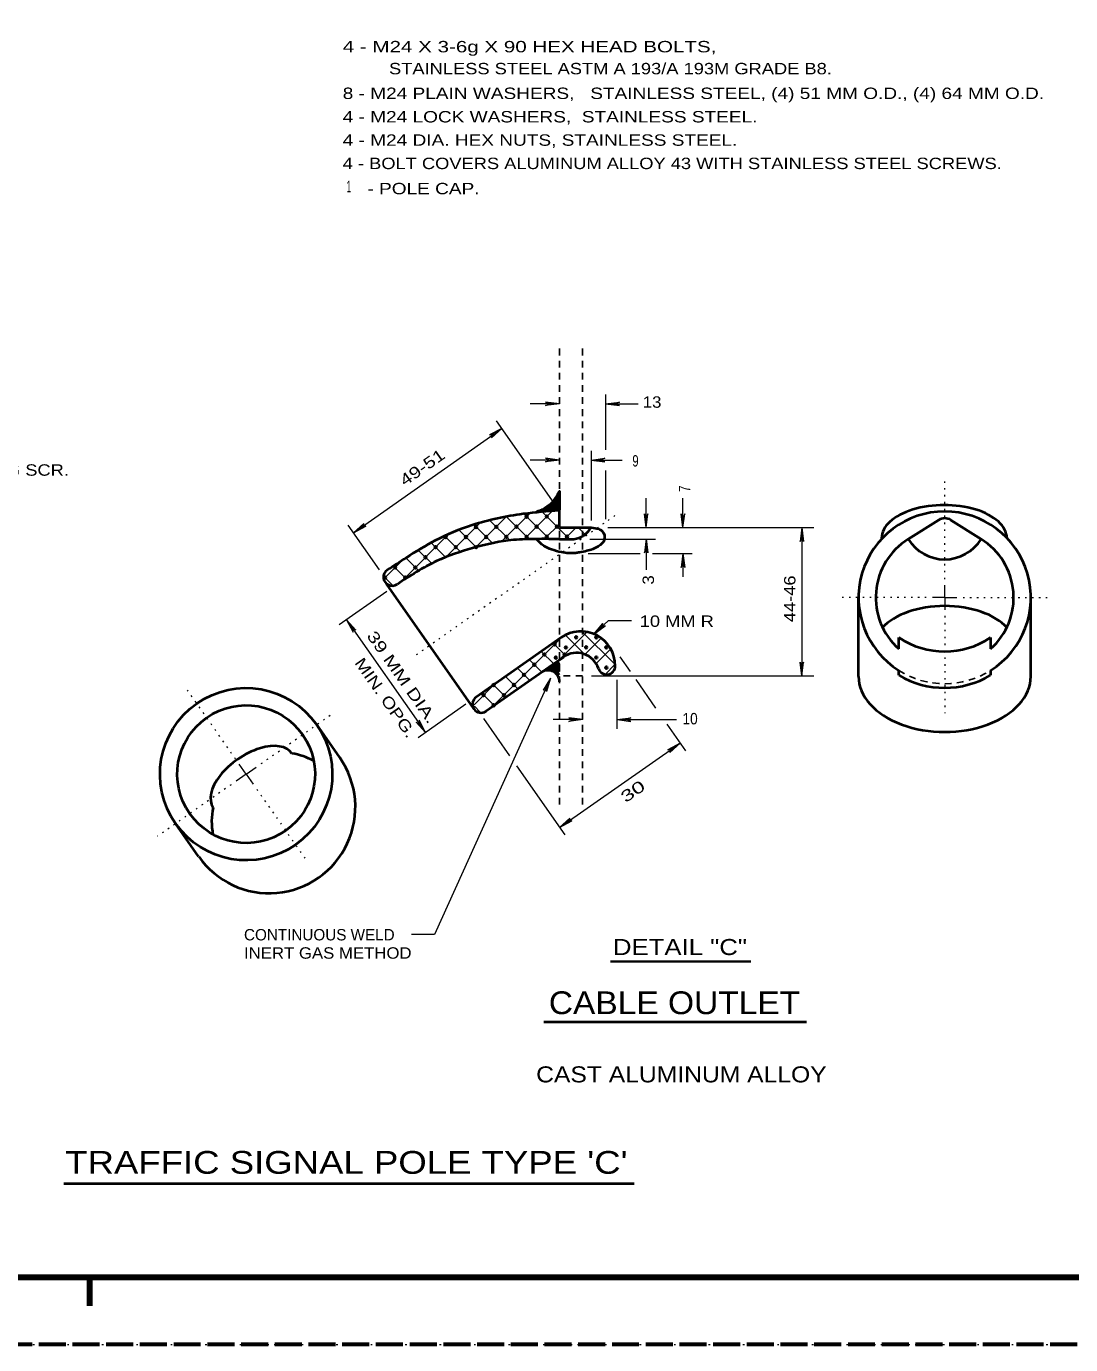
# Model space of a CAD drawing. Extents: x 312583 to 312854, y 144419 to 144597.
# Drawn here: x 312723.1 to 312792.8, y 144418.6 to 144506.5 of the extents above; entities that cross this region are included whole.
import ezdxf
from ezdxf.enums import TextEntityAlignment as Align

# ---------------------------------------------------------------- set-up
doc = ezdxf.new("R2010")
doc.units = 0
doc.header["$LTSCALE"] = 0.3
doc.header["$PDMODE"] = 32
doc.header["$PDSIZE"] = 0.15
for name, pattern in [('DOTTED', [1.5, 0.3, -1.2]), ('LONG_DASHED', [7.5, 6, -1.5]), ('SHORT_DASHED', [2.7, 1.5, -1.2])]:
    doc.linetypes.add(name, pattern=pattern)
for name, color, linetype, lineweight in [('1', 7, 'Continuous', 35), ('2', 7, 'Continuous', 13), ('62', 7, 'DOTTED', 13), ('63', 7, 'LONG_DASHED', 60)]:
    doc.layers.add(name, color=color, linetype=linetype, lineweight=lineweight)

msp = doc.modelspace()

# ---------------------------------------------------------------- linework, layer by layer
at = {"layer": '1', "linetype": 'SHORT_DASHED', "lineweight": 25}
for p, q in [((312758.6957, 144454.6164), (312758.6957, 144485.3597)), ((312760.229, 144454.6164), (312760.229, 144485.3597)), ((312760.229, 144463.1954), (312758.6957, 144463.1954))]:
    msp.add_line(p, q, dxfattribs=at)
at = {"layer": '1', "linetype": 'DOTTED', "lineweight": 13}
msp.add_line((312762.3987, 144473.8981), (312748.9897, 144464.4987), dxfattribs=at)
at = {"layer": '1', "lineweight": 13}
for p, q in [((312753.0913, 144471.7591), (312755.1077, 144473.7831)), ((312754.8547, 144472.1807), (312756.733, 144474.0591)), ((312756.6487, 144472.3341), (312755.192, 144473.7907)), ((312756.3267, 144472.3111), (312758.2203, 144474.2047)), ((312757.975, 144472.3571), (312756.342, 144473.9977)), ((312759.3397, 144472.3417), (312757.5457, 144474.1511)), ((312751.1747, 144471.1841), (312753.3597, 144473.3691)), ((312753.1527, 144471.7667), (312751.9567, 144472.9704)), ((312754.2413, 144472.0351), (312753.007, 144473.2694)), ((312755.3837, 144472.2497), (312754.0573, 144473.5684)), ((312757.722, 144472.3571), (312758.688, 144473.3231)), ((312759.0483, 144472.3417), (312759.7997, 144473.0931)), ((312760.3363, 144472.7021), (312759.9453, 144473.1007)), ((312748.1923, 144469.5511), (312751.3203, 144472.6791)), ((312751.0673, 144471.1457), (312750.132, 144472.0887)), ((312752.087, 144471.4831), (312751.0367, 144472.5334)), ((312749.281, 144470.2257), (312748.4377, 144471.0691)), ((312750.155, 144470.7164), (312749.2733, 144471.5904)), ((312747.004, 144469.7044), (312748.269, 144470.9694)), ((312748.4453, 144469.7044), (312747.6173, 144470.5324)), ((312747.5407, 144469.2674), (312746.9963, 144469.8117)), ((312754.1723, 144461.1101), (312758.872, 144465.8097)), ((312758.6497, 144464.2457), (312760.5433, 144466.1317)), ((312760.3977, 144464.6367), (312759.0713, 144465.9477)), ((312762.4217, 144463.9697), (312760.1907, 144466.1701)), ((312759.102, 144464.5677), (312758.2817, 144465.3881)), ((312760.3823, 144464.6367), (312761.471, 144465.7254)), ((312761.1337, 144464.0311), (312762.115, 144465.0124)), ((312757.515, 144463.4484), (312756.687, 144464.2764)), ((312758.3123, 144464.0004), (312757.4843, 144464.8361)), ((312755.9203, 144462.3367), (312755.0923, 144463.1647)), ((312756.7177, 144462.8887), (312755.8897, 144463.7244)), ((312761.7393, 144463.3027), (312762.4217, 144463.9851)), ((312752.9993, 144461.2787), (312754.387, 144462.6664)), ((312755.1307, 144461.7694), (312754.3027, 144462.5974)), ((312754.3333, 144461.2174), (312753.5053, 144462.0454)), ((312753.4057, 144460.7881), (312753.03, 144461.1714))]:
    msp.add_line(p, q, dxfattribs=at)
at = {"layer": '1', "lineweight": 40}
for p, q in [((312758.6957, 144473.0931), (312758.6957, 144474.2431)), ((312758.6957, 144473.0931), (312760.804, 144473.0931)), ((312783.9957, 144473.5991), (312781.9563, 144472.3264)), ((312784.8083, 144473.5991), (312786.84, 144472.3264)), ((312758.6957, 144472.3264), (312759.654, 144472.3264)), ((312752.9533, 144461.0487), (312747.1497, 144469.3517)), ((312778.652, 144463.1647), (312778.652, 144468.4241)), ((312790.1443, 144463.1647), (312790.1443, 144468.4241)), ((312758.803, 144465.7561), (312753.1297, 144461.7924)), ((312781.3353, 144464.9971), (312781.3353, 144465.7561)), ((312787.4687, 144464.9971), (312787.4687, 144465.7561)), ((312758.9563, 144464.4604), (312753.7967, 144460.8417)), ((312757.4843, 144463.4331), (312758.9563, 144464.4604)), ((312757.9443, 144463.5711), (312758.6957, 144464.0924)), ((312758.1513, 144463.5404), (312758.6957, 144463.9161)), ((312758.3123, 144463.4714), (312758.6957, 144463.7397)), ((312758.435, 144463.3794), (312758.6957, 144463.5557)), ((312758.5347, 144463.2721), (312758.6957, 144463.3871)), ((312758.619, 144463.1417), (312758.6957, 144463.2031)), ((312781.3353, 144463.2414), (312781.3353, 144463.5711)), ((312787.4687, 144463.2414), (312787.4687, 144463.5711)), ((312744.037, 144457.7521), (312742.496, 144459.9524)), ((312734.6147, 144451.1511), (312733.0737, 144453.3437)), ((312763.6794, 144429.3029), (312725.619, 144429.3029))]:
    msp.add_line(p, q, dxfattribs=at)
at = {"layer": '1', "lineweight": 158}
for p, q in [((312616.5, 144423.0846), (312849, 144423.0846)), ((312727.35, 144421.1646), (312727.35, 144423.0846))]:
    msp.add_line(p, q, dxfattribs=at)
at = {"layer": '1', "lineweight": 40}
for centre, radius, start, end in [((312784.4005, 144468.4256), 5.7469, 302.26476, 237.73524), ((312784.4005, 144472.9493), 0.7667, 57.96874, 122.03126), ((312759.4572, 144473.8705), 1.5564, 277.20711, 330.03225), ((312784.4005, 144468.4256), 4.6, 122.03776, 228.18882), ((312784.4005, 144473.8536), 2.8794, 212.03126, 327.96874), ((312784.4005, 144468.4256), 4.6, 311.81031, 57.96224), ((312747.5267, 144469.7894), 0.5768, 125.00164, 305.00164), ((312760.1186, 144463.871), 2.3, 0, 125.01416), ((312784.4005, 144470.3718), 5.5403, 236.39125, 303.60875), ((312759.8395, 144463.2042), 1.5333, 18.24978, 124.99202), ((312757.929, 144462.8037), 0.7667, 0, 125.00321), ((312761.8421, 144463.8685), 0.5765, 198.353, 0), ((312784.4005, 144468.4256), 6.0201, 239.38652, 300.62404), ((312753.4639, 144461.3171), 0.5768, 125.04193, 305.04193)]:
    msp.add_arc(centre, radius, start, end, dxfattribs=at)
at = {"layer": '1', "linetype": 'SHORT_DASHED', "lineweight": 25}
msp.add_arc((312784.4005, 144468.4256), 5.7469, 237.73524, 302.26476, dxfattribs=at)
at = {"layer": '1', "lineweight": 40}
for centre, major_axis, ratio, start_param, end_param in [((312784.3667, 144472.3877), (4.1799, 0.0061), 0.5283, 6.2831853, 9.424778), ((312784.4005, 144465.3099), (-4.5969, 0), 0.555704, 3.5912894, 5.8336047), ((312784.4005, 144463.1632), (-5.7469, 0), 0.64461, 6.2831853, 9.424778), ((312738.1981, 144456.2417), (-2.6189, -1.8001), 0.537251, 3.1255912, 6.2961342), ((312740.081, 144453.5001), (-3.7634, -2.6378), 0.999836, 3.598371, 3.9338982), ((312739.3266, 144454.4508), (-4.7079, -3.3002), 0.999869, 0.0001305, 3.1417232), ((312740.081, 144453.5001), (-3.7634, -2.6378), 0.999836, 5.4703118, 5.8646097)]:
    msp.add_ellipse(centre, major_axis=major_axis, ratio=ratio, start_param=start_param, end_param=end_param, dxfattribs=at)
for major_axis, ratio in [((-4.7079, -3.3002), 0.999869), ((-3.7634, -2.6378), 0.999836)]:
    msp.add_ellipse((312737.7871, 144456.6465), major_axis=major_axis, ratio=ratio, dxfattribs=at)
for points in [[(312758.6957, 144474.2431), (312756.273, 144474.0054), (312752.869, 144473.2541), (312750.3927, 144472.2267), (312748.4683, 144471.0844), (312747.1957, 144470.2564)], [(312760.804, 144473.0931), (312761.3253, 144473.0011), (312761.5323, 144472.8784), (312761.6857, 144472.2727), (312761.287, 144471.8357), (312760.5203, 144471.5367), (312760.0297, 144471.4371), (312759.7843, 144471.3987), (312758.8337, 144471.4524), (312758.159, 144471.6364), (312757.653, 144471.8817), (312757.1777, 144472.3111)], [(312758.6957, 144472.3264), (312756.8097, 144472.3264), (312755.2457, 144472.2267), (312752.892, 144471.7207), (312750.5153, 144470.8697), (312747.855, 144469.3134)]]:
    msp.add_spline(points, degree=3, dxfattribs=at)
at = {"layer": '1'}
for p in [(312756.503, 144473.8291), (312757.8523, 144473.8367), (312753.1297, 144473.1391), (312754.479, 144473.1467), (312755.8283, 144473.1544), (312757.1777, 144473.1621), (312758.527, 144473.1621), (312751.1057, 144472.4644), (312752.455, 144472.4644), (312753.8043, 144472.4721), (312755.1537, 144472.4797), (312756.503, 144472.4797), (312757.8523, 144472.4874), (312759.2017, 144472.4951), (312749.7563, 144471.1151), (312750.431, 144471.7897), (312751.7803, 144471.7897), (312753.1297, 144471.7897), (312747.7323, 144470.4327), (312749.0817, 144470.4327), (312747.05, 144469.7504), (312748.3993, 144469.7581), (312759.8073, 144465.7714), (312761.1567, 144465.7791), (312758.366, 144465.3037), (312759.125, 144465.0967), (312760.4743, 144465.1044), (312761.8237, 144465.1044), (312757.0167, 144463.9467), (312757.6913, 144464.6291), (312758.4503, 144464.4221), (312759.0407, 144464.6291), (312761.149, 144464.4297), (312756.3343, 144463.2721), (312761.8237, 144463.7551), (312754.3103, 144462.5897), (312755.6597, 144462.5974), (312753.6357, 144461.9151), (312754.985, 144461.9151), (312754.3027, 144461.2404)]:
    msp.add_point(p, dxfattribs=at)
at = {"layer": '2'}
for p, q in [((312761.7623, 144481.9634), (312761.7623, 144478.2834)), ((312758.6957, 144481.3501), (312756.7407, 144481.3501)), ((312757.768, 144481.4651), (312758.067, 144481.3501)), ((312758.6957, 144481.3501), (312757.768, 144481.4651)), ((312757.768, 144481.2351), (312758.067, 144481.3501)), ((312758.6957, 144481.3501), (312757.768, 144481.2351)), ((312761.7623, 144481.3501), (312762.69, 144481.4651)), ((312761.7623, 144481.3501), (312763.9414, 144481.3501)), ((312761.7623, 144481.3501), (312762.69, 144481.2351)), ((312762.69, 144481.4651), (312762.391, 144481.3501)), ((312762.69, 144481.2351), (312762.391, 144481.3501)), ((312758.3507, 144474.7337), (312754.4943, 144480.2231)), ((312744.9417, 144472.7481), (312754.847, 144479.7171)), ((312754.847, 144479.7171), (312754.0267, 144479.2801)), ((312754.0267, 144479.2801), (312754.3333, 144479.3567)), ((312754.847, 144479.7171), (312754.157, 144479.0884)), ((312754.157, 144479.0884), (312754.3333, 144479.3567)), ((312760.804, 144478.2144), (312760.804, 144473.5607)), ((312758.6957, 144477.6011), (312756.7407, 144477.6011)), ((312757.768, 144477.7161), (312758.067, 144477.6011)), ((312758.6957, 144477.6011), (312757.768, 144477.7161)), ((312757.768, 144477.4861), (312758.067, 144477.6011)), ((312758.6957, 144477.6011), (312757.768, 144477.4861)), ((312760.804, 144477.6011), (312761.7317, 144477.7161)), ((312760.804, 144477.6011), (312762.8784, 144477.6011)), ((312760.804, 144477.6011), (312761.7317, 144477.4861)), ((312761.7317, 144477.7161), (312761.4403, 144477.6011)), ((312761.7317, 144477.4861), (312761.4403, 144477.6011)), ((312761.7623, 144476.9111), (312761.7623, 144473.6681)), ((312764.484, 144473.0931), (312764.484, 144475.0481)), ((312766.9373, 144473.0931), (312766.9373, 144475.0481)), ((312764.369, 144474.0207), (312764.484, 144473.7217)), ((312764.484, 144473.0931), (312764.369, 144474.0207)), ((312764.599, 144474.0207), (312764.484, 144473.7217)), ((312764.484, 144473.0931), (312764.599, 144474.0207)), ((312766.8223, 144474.0207), (312766.9373, 144473.7217)), ((312766.9373, 144473.0931), (312766.8223, 144474.0207)), ((312767.0523, 144474.0207), (312766.9373, 144473.7217)), ((312766.9373, 144473.0931), (312767.0523, 144474.0207)), ((312746.682, 144470.2794), (312744.589, 144473.2541)), ((312744.9417, 144472.7481), (312745.6393, 144473.3767)), ((312744.9417, 144472.7481), (312745.7697, 144473.1851)), ((312745.6393, 144473.3767), (312745.463, 144473.1084)), ((312745.7697, 144473.1851), (312745.463, 144473.1084)), ((312761.931, 144473.0931), (312775.662, 144473.0931)), ((312774.8723, 144473.0931), (312774.7497, 144472.1654)), ((312774.8723, 144473.0931), (312774.8723, 144463.1954)), ((312774.8723, 144473.0931), (312774.9873, 144472.1654)), ((312760.7273, 144472.3264), (312765.0973, 144472.3264)), ((312764.484, 144472.3341), (312764.369, 144471.4064)), ((312764.484, 144472.3341), (312764.484, 144470.2863)), ((312764.484, 144472.3341), (312764.599, 144471.4064)), ((312774.7497, 144472.1654), (312774.8723, 144472.4644)), ((312774.9873, 144472.1654), (312774.8723, 144472.4644)), ((312760.62, 144471.3681), (312764.0853, 144471.3681)), ((312764.369, 144471.4064), (312764.484, 144471.6977)), ((312764.599, 144471.4064), (312764.484, 144471.6977)), ((312764.9133, 144471.3681), (312767.5507, 144471.3681)), ((312766.9373, 144471.3604), (312766.8223, 144470.4404)), ((312766.9373, 144471.3604), (312766.9373, 144469.8117)), ((312766.9373, 144471.3604), (312767.0523, 144470.4404)), ((312766.8223, 144470.4404), (312766.9373, 144470.7317)), ((312767.0523, 144470.4404), (312766.9373, 144470.7317)), ((312747.1727, 144468.8381), (312743.9833, 144466.5994)), ((312784.402, 144468.4241), (312783.5817, 144468.4241)), ((312784.402, 144468.4241), (312784.402, 144469.2444)), ((312784.402, 144468.4241), (312784.402, 144469.2444)), ((312784.402, 144468.4241), (312785.2147, 144468.4241)), ((312784.402, 144468.4241), (312784.402, 144467.6114)), ((312744.4817, 144466.9444), (312749.764, 144459.4234)), ((312744.4817, 144466.9444), (312744.9187, 144466.1241)), ((312744.4817, 144466.9444), (312745.1103, 144466.2544)), ((312760.9957, 144465.9937), (312761.9693, 144466.9061)), ((312760.9957, 144465.9937), (312761.5937, 144466.7067)), ((312761.5937, 144466.7067), (312761.4557, 144466.4231)), ((312761.9693, 144466.9061), (312763.5027, 144466.9061)), ((312744.9187, 144466.1241), (312744.8497, 144466.4307)), ((312745.1103, 144466.2544), (312744.8497, 144466.4307)), ((312760.9957, 144465.9937), (312761.747, 144466.5457)), ((312761.747, 144466.5457), (312761.4557, 144466.4231)), ((312762.7283, 144464.4757), (312763.4183, 144463.4867)), ((312774.7497, 144464.1231), (312774.8723, 144463.8241)), ((312774.8723, 144463.1954), (312774.7497, 144464.1231)), ((312774.9873, 144464.1231), (312774.8723, 144463.8241)), ((312774.8723, 144463.1954), (312774.9873, 144464.1231)), ((312760.8423, 144463.1954), (312775.662, 144463.1954)), ((312758.0977, 144463.0421), (312750.362, 144445.9377)), ((312758.0977, 144463.0421), (312757.6147, 144462.2447)), ((312757.6147, 144462.2447), (312757.8447, 144462.4671)), ((312758.0977, 144463.0421), (312757.8217, 144462.1527)), ((312757.8217, 144462.1527), (312757.8447, 144462.4671)), ((312762.529, 144462.9271), (312762.529, 144459.6687)), ((312763.794, 144462.9501), (312765.1127, 144461.0564)), ((312752.455, 144461.3094), (312749.2657, 144459.0707)), ((312749.143, 144460.1134), (312749.4037, 144459.9371)), ((312749.764, 144459.4234), (312749.143, 144460.1134)), ((312749.327, 144460.2437), (312749.4037, 144459.9371)), ((312749.764, 144459.4234), (312749.327, 144460.2437)), ((312753.6357, 144460.3511), (312755.3683, 144457.8671)), ((312760.2443, 144460.2821), (312758.2817, 144460.2821)), ((312759.3167, 144460.3971), (312759.608, 144460.2821)), ((312760.2443, 144460.2821), (312759.3167, 144460.3971)), ((312759.3167, 144460.1671), (312759.608, 144460.2821)), ((312760.2443, 144460.2821), (312759.3167, 144460.1671)), ((312762.5367, 144460.2821), (312763.4643, 144460.3971)), ((312762.5367, 144460.2821), (312766.4934, 144460.2821)), ((312762.5367, 144460.2821), (312763.4643, 144460.1671)), ((312763.4643, 144460.3971), (312763.1653, 144460.2821)), ((312763.4643, 144460.1671), (312763.1653, 144460.2821)), ((312765.8563, 144459.9907), (312767.0983, 144458.2044)), ((312758.7033, 144453.0907), (312766.7457, 144458.7104)), ((312766.7457, 144458.7104), (312765.9253, 144458.2734)), ((312765.9253, 144458.2734), (312766.232, 144458.3501)), ((312766.7457, 144458.7104), (312766.0557, 144458.0817)), ((312766.0557, 144458.0817), (312766.232, 144458.3501)), ((312737.7887, 144456.6481), (312737.321, 144457.3151)), ((312737.7887, 144456.6481), (312737.321, 144457.3151)), ((312737.7887, 144456.6481), (312738.4557, 144457.1157)), ((312755.8207, 144457.2077), (312759.0483, 144452.5924)), ((312737.7887, 144456.6481), (312737.1217, 144456.1804)), ((312737.7887, 144456.6481), (312738.2563, 144455.9811)), ((312758.7033, 144453.0907), (312759.3933, 144453.7117)), ((312758.7033, 144453.0907), (312759.5237, 144453.5277)), ((312759.3933, 144453.7117), (312759.217, 144453.4511)), ((312759.5237, 144453.5277), (312759.217, 144453.4511)), ((312750.362, 144445.9377), (312748.8287, 144445.9377))]:
    msp.add_line(p, q, dxfattribs=at)
at = {"layer": '2', "linetype": 'DOTTED'}
for p, q in [((312784.402, 144469.6507), (312784.402, 144476.1751)), ((312783.1753, 144468.4241), (312777.226, 144468.4241)), ((312785.6287, 144468.4241), (312791.5013, 144468.4241)), ((312784.402, 144467.1974), (312784.402, 144460.7191)), ((312737.0833, 144457.6524), (312733.7177, 144462.4671)), ((312738.793, 144457.3534), (312743.623, 144460.7344)), ((312736.7843, 144455.9427), (312731.8777, 144452.5081)), ((312738.494, 144455.6437), (312741.8213, 144450.8751))]:
    msp.add_line(p, q, dxfattribs=at)
at = {"layer": '2', "lineweight": 53}
for p, q in [((312757.7987, 144474.2201), (312758.688, 144475.1094)), ((312758.1283, 144474.2431), (312758.688, 144474.8027)), ((312758.5883, 144475.3087), (312758.688, 144475.4084)), ((312757.469, 144474.1894), (312757.5917, 144474.3121)), ((312758.458, 144474.2661), (312758.688, 144474.5037))]:
    msp.add_line(p, q, dxfattribs=at)
at = {"layer": '2', "lineweight": 35}
msp.add_line((312762.106, 144444.1523), (312771.4606, 144444.1523), dxfattribs=at)
at = {"layer": '2', "lineweight": 40}
msp.add_line((312757.6607, 144440.1187), (312775.1713, 144440.1187), dxfattribs=at)
msp.add_lwpolyline([(312757.147, 144474.1204), (312757.561, 144474.2967), (312757.883, 144474.5191), (312758.228, 144474.7721), (312758.5193, 144475.1631), (312758.688, 144475.5234), (312758.688, 144474.2814), (312757.2543, 144474.1817)], close=True, dxfattribs=at)
msp.add_arc((312756.415, 144476.4954), 2.4833, 287.21861, 335.99154, dxfattribs=at)
at = {"layer": '62'}
msp.add_lwpolyline([(312601.2, 144418.5846), (312853.5, 144418.5846), (312853.5, 144596.7846)], dxfattribs=at)
at = {"layer": '63'}
msp.add_line((312851.75, 144418.5846), (312583.526, 144418.5846), dxfattribs=at)

# ---------------------------------------------------------------- texts
at = {"layer": '2'}
for s, width, p in [('4 - M24 X 3-6g X 90 HEX HEAD BOLTS,  ', 1.35, (312744.2309, 144504.8017)), ('STAINLESS STEEL ASTM A 193/A 193M GRADE B8.', 1.2, (312747.3205, 144503.3374)), ('8 - M24 PLAIN WASHERS,   STAINLESS STEEL, (4) 51 MM O.D., (4) 64 MM O.D. ', 1.25, (312744.2309, 144501.689)), ('4 - M24 LOCK WASHERS,  STAINLESS STEEL.  ', 1.25, (312744.2309, 144500.125)), ('4 - M24 DIA. HEX NUTS, STAINLESS STEEL.', 1.25, (312744.2309, 144498.5687)), ('4 - BOLT COVERS ALUMINUM ALLOY 43 WITH STAINLESS STEEL SCREWS.  ', 1.2, (312744.2309, 144497.0124)), ('1', 0.5, (312744.4934, 144495.4714)), ('- POLE CAP. ', 1.25, (312745.8792, 144495.3334)), ('13 ', 1.1, (312764.2546, 144481.0919)), ('STN. STL. SELF-TAPPING SCR.', 1.2, (312707.8665, 144476.5563)), ('9', 0.75, (312763.5554, 144477.1692)), ('10 MM R', 1.2, (312764.0508, 144466.4716)), ('10', 0.9, (312766.9021, 144459.9671)), ('INERT GAS METHOD', 1.1, (312737.6446, 144444.3333))]:
    msp.add_text(s, height=0.76, dxfattribs=dict(at, width=width)).set_placement(p)
for s, rotation, width, p in [('49-51 ', 35.155, 1.3, (312748.3756, 144475.8297)), ('7', 90, 0.75, (312767.4222, 144475.4732)), ('3 ', 90, 1.1, (312765.001, 144469.2913)), ('44-46', 90, 1.2, (312774.4405, 144466.7825)), ('39 MM DIA.', 305.046, 1.35, (312745.7967, 144465.8664)), ('MIN. OPG.', 305.059, 1.25, (312744.9852, 144464.0699)), ('30', 34.843, 1.5, (312763.1111, 144454.7022))]:
    msp.add_text(s, height=0.76, rotation=rotation, dxfattribs=dict(at, width=width)).set_placement(p)
msp.add_text('CONTINUOUS WELD', height=0.76, dxfattribs=at).set_placement((312737.6446, 144445.5533))
for s, height, width, p in [('DETAIL "C"', 1.07, 1.2, (312766.7365, 144444.5765)), ('CABLE OUTLET', 1.52, 1.1, (312766.37, 144440.6344)), ('CAST ALUMINUM ALLOY', 1.07, 1.15, (312766.8306, 144436.0803)), ("TRAFFIC SIGNAL POLE TYPE 'C'", 1.52, 1.2, (312744.4782, 144429.9834))]:
    msp.add_text(s, height=height, dxfattribs=dict(at, width=width)).set_placement(p, align=Align.CENTER)

doc.saveas('drawing.dxf')
